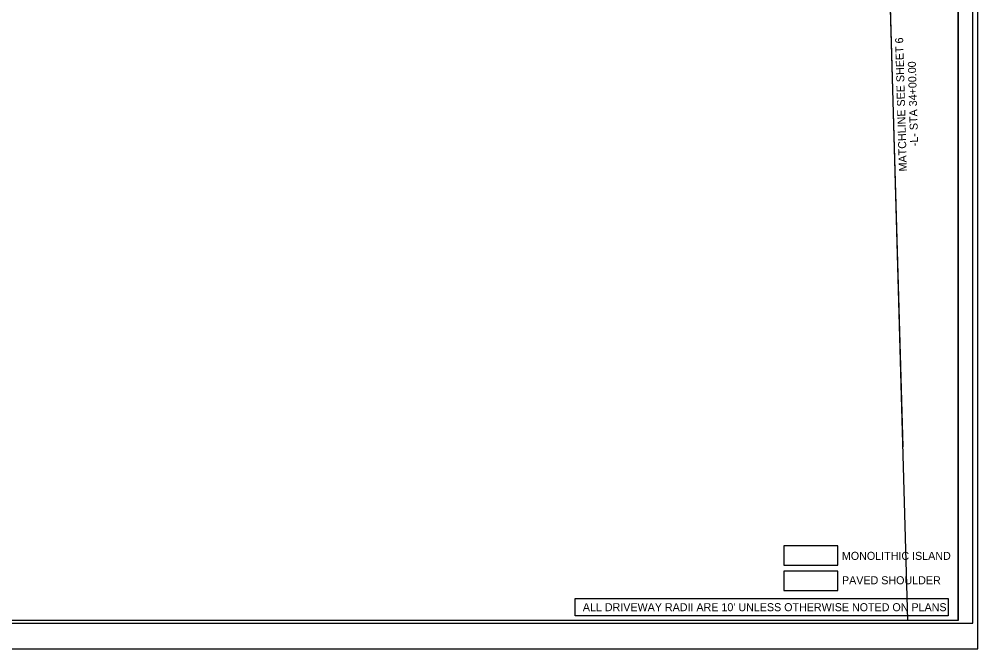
# Model space of a CAD drawing. Extents: x 1756263 to 1758375, y 736518 to 737683.
# Drawn here: x 1757319 to 1758158, y 736518 to 737068 of the extents above; entities that cross this region are included whole.
import ezdxf

# ---------------------------------------------------------------- set-up
doc = ezdxf.new("R2010")
doc.units = 0
for name, color, linetype in [('Matchline', 7, 'Continuous'), ('Matchline Text', 7, 'Continuous'), ('Old_Level_40', 7, 'Continuous'), ('Prop DSN Text', 7, 'Continuous'), ('Prop Grid Mask', 7, 'Continuous'), ('Prop Shade Light', 7, 'Continuous'), ('Prop Shade Medium', 7, 'Continuous'), ('Scratch_Level_3', 7, 'Continuous'), ('Sheet Border Standard 30in CELL', 7, 'Continuous'), ('Sheet Clip Boundary CELL', 7, 'Continuous'), ('Sheet Cutting Line CELL', 7, 'Continuous'), ('Sheet Plot Border Inside CELL', 7, 'Continuous'), ('Sheet Plot Border Outside CELL', 7, 'Continuous')]:
    doc.layers.add(name, color=color, linetype=linetype)

msp = doc.modelspace()

# ---------------------------------------------------------------- linework, layer by layer
at = {"layer": 'Matchline'}
msp.add_line((1758092.09, 736694.03), (1758075.16, 737290.21), dxfattribs=at)
at = {"layer": 'Old_Level_40'}
for points in [[(1758035.23, 736607.61), (1757987.9, 736607.61), (1757987.9, 736590.67), (1758035.23, 736590.67)], [(1758035.23, 736585.66), (1757987.9, 736585.66), (1757987.9, 736568.72), (1758035.23, 736568.72)]]:
    msp.add_lwpolyline(points, close=True, dxfattribs=at)
msp.add_lwpolyline([(1758035.23, 736585.66), (1757987.9, 736585.66), (1757987.9, 736568.72), (1758035.23, 736568.72), (1758035.23, 736585.66)], dxfattribs=at)
at = {"layer": 'Prop Grid Mask'}
msp.add_lwpolyline([(1757805.57, 736561.58), (1758131.53, 736561.58), (1758131.53, 736546.58), (1757805.57, 736546.58)], close=True, dxfattribs=at)
at = {"layer": 'Prop Shade Light'}
msp.add_lwpolyline([(1758035.23, 736585.66), (1757987.9, 736585.66), (1757987.9, 736568.72), (1758035.23, 736568.72), (1758035.23, 736585.66)], dxfattribs=at)
msp.add_lwpolyline([(1758035.23, 736585.66), (1757987.9, 736585.66), (1757987.9, 736568.72), (1758035.23, 736568.72)], close=True, dxfattribs=at)
at = {"layer": 'Prop Shade Medium'}
msp.add_lwpolyline([(1758035.23, 736607.61), (1757987.9, 736607.61), (1757987.9, 736590.67), (1758035.23, 736590.67), (1758035.23, 736607.61)], dxfattribs=at)
at = {"layer": 'Scratch_Level_3'}
msp.add_lwpolyline([(1756640.54, 736542.73), (1758140.29, 736542.73), (1758140.29, 737295.24), (1757940.47, 737295.24), (1757940.47, 737592.73), (1756640.54, 737592.73)], close=True, dxfattribs=at)
at = {"layer": 'Sheet Border Standard 30in CELL'}
msp.add_lwpolyline([(1758140.51, 737592.73), (1756640.51, 737592.73), (1756640.51, 736542.73), (1758140.51, 736542.73)], close=True, dxfattribs=at)
at = {"layer": 'Sheet Clip Boundary CELL'}
msp.add_lwpolyline([(1756640.54, 736751.68), (1756640.54, 736542.73), (1758096.38, 736542.73), (1758075.02, 737295.21), (1757940.47, 737295.24), (1757940.48, 737592.73), (1756779.65, 737592.73)], close=True, dxfattribs=at)
at = {"layer": 'Sheet Cutting Line CELL'}
msp.add_line((1756473.51, 736517.73), (1758157.51, 736517.73), dxfattribs=at)
at = {"layer": 'Sheet Plot Border Inside CELL'}
msp.add_lwpolyline([(1758153.01, 737595.28), (1756486.51, 737595.28), (1756486.51, 736540.18), (1758153.01, 736540.18)], close=True, dxfattribs=at)
at = {"layer": 'Sheet Plot Border Outside CELL'}
msp.add_lwpolyline([(1758157.51, 737617.73), (1756473.51, 737617.73), (1756473.51, 736517.73), (1758157.51, 736517.73)], close=True, dxfattribs=at)

# ---------------------------------------------------------------- texts
at = {"layer": 'Matchline Text'}
for s, p in [('MATCHLINE SEE SHEET 6 ', (1758095.5, 736934.85)), ('-L- STA 34+00.00', (1758105.38, 736956.86))]:
    msp.add_text(s, height=7, rotation=91.62654, dxfattribs=at).set_placement(p)
at = {"layer": 'Prop DSN Text'}
for s, p in [('MONOLITHIC ISLAND', (1758038.67, 736595.42)), ('PAVED SHOULDER', (1758038.74, 736574.11))]:
    msp.add_text(s, height=7, dxfattribs=at).set_placement(p)
msp.add_text("ALL DRIVEWAY RADII ARE 10' UNLESS OTHERWISE NOTED ON PLANS.", height=7, rotation=359.9997, dxfattribs=at).set_placement((1757812.13, 736550.58))

doc.saveas('drawing.dxf')
